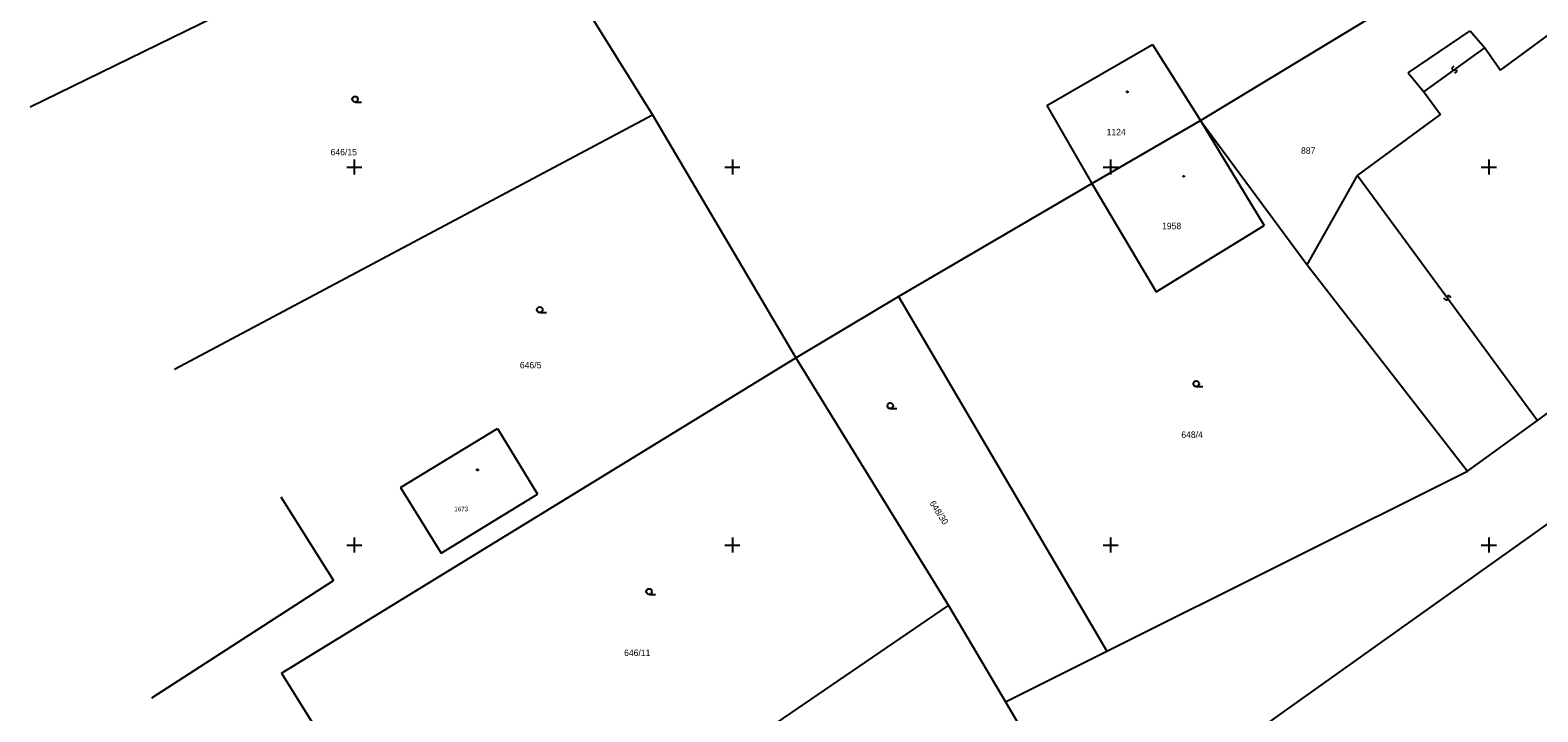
# Model space of a CAD drawing. Extents: x -492811 to -492366, y -1127107 to -1126748.
# Drawn here: x -492797.1 to -492717.4, y -1126848.8 to -1126812.8 of the extents above; entities that cross this region are included whole.
import ezdxf

# ---------------------------------------------------------------- set-up
doc = ezdxf.new("R2010")
doc.units = 0
doc.layers.add('katastrální mapa', color=7, linetype='Continuous')
doc.layers.add('síť', color=7, linetype='Continuous')

msp = doc.modelspace()

# ---------------------------------------------------------------- linework, layer by layer
at = {"layer": 'katastrální mapa'}
for p, q in [((-492735.24, -1126817.53), (-492712.31, -1126803.62)), ((-492771.89, -1126804.96), (-492764.22, -1126817.23)), ((-492797.14, -1126816.82), (-492778.84, -1126807.86)), ((-492719.38, -1126814.88), (-492714.08, -1126810.97)), ((-492724.26, -1126815.01), (-492720.98, -1126812.79)), ((-492720.98, -1126812.79), (-492720.21, -1126813.69)), ((-492743.37, -1126816.75), (-492737.78, -1126813.52)), ((-492737.78, -1126813.52), (-492735.24, -1126817.53)), ((-492723.44, -1126816.02), (-492720.21, -1126813.69)), ((-492720.21, -1126813.69), (-492719.38, -1126814.88)), ((-492724.26, -1126815.01), (-492723.44, -1126816.02)), ((-492721.94, -1126814.76), (-492721.95, -1126814.82)), ((-492721.95, -1126814.82), (-492721.92, -1126814.85)), ((-492721.84, -1126814.67), (-492721.94, -1126814.76)), ((-492721.92, -1126814.85), (-492721.87, -1126814.86)), ((-492721.87, -1126814.86), (-492721.78, -1126814.85)), ((-492721.71, -1126814.95), (-492721.81, -1126815.04)), ((-492721.78, -1126814.85), (-492721.73, -1126814.86)), ((-492721.73, -1126814.86), (-492721.7, -1126814.89)), ((-492721.7, -1126814.89), (-492721.71, -1126814.95)), ((-492779.96, -1126816.56), (-492779.61, -1126816.56)), ((-492739.15, -1126815.99), (-492739.09, -1126815.99)), ((-492739.15, -1126816.05), (-492739.15, -1126815.99)), ((-492739.09, -1126816.05), (-492739.15, -1126816.05)), ((-492739.09, -1126815.99), (-492739.09, -1126816.05)), ((-492723.44, -1126816.02), (-492722.56, -1126817.22)), ((-492789.5, -1126830.69), (-492764.22, -1126817.23)), ((-492764.22, -1126817.23), (-492756.64, -1126830.09)), ((-492743.37, -1126816.75), (-492741, -1126820.87)), ((-492726.94, -1126820.45), (-492722.56, -1126817.22)), ((-492741, -1126820.87), (-492735.24, -1126817.53)), ((-492735.24, -1126817.53), (-492729.6, -1126825.18)), ((-492735.24, -1126817.53), (-492731.88, -1126823.09)), ((-492736.17, -1126820.46), (-492736.11, -1126820.46)), ((-492736.17, -1126820.52), (-492736.17, -1126820.46)), ((-492736.11, -1126820.52), (-492736.17, -1126820.52)), ((-492736.11, -1126820.46), (-492736.11, -1126820.52)), ((-492729.6, -1126825.18), (-492726.94, -1126820.45)), ((-492726.94, -1126820.45), (-492717.43, -1126833.41)), ((-492751.22, -1126826.85), (-492741, -1126820.87)), ((-492741, -1126820.87), (-492737.59, -1126826.61)), ((-492737.59, -1126826.61), (-492731.88, -1126823.09)), ((-492733.15, -1126850.46), (-492697, -1126824.72)), ((-492729.6, -1126825.18), (-492721.12, -1126836.09)), ((-492756.64, -1126830.09), (-492751.22, -1126826.85)), ((-492751.22, -1126826.85), (-492740.2, -1126845.62)), ((-492722.27, -1126827.05), (-492722.37, -1126826.94)), ((-492722.18, -1126826.83), (-492722.19, -1126826.89)), ((-492722.19, -1126826.89), (-492722.18, -1126826.97)), ((-492722.18, -1126826.97), (-492722.19, -1126827.03)), ((-492722.15, -1126826.81), (-492722.18, -1126826.83)), ((-492722.1, -1126826.81), (-492722.15, -1126826.81)), ((-492722, -1126826.92), (-492722.1, -1126826.81)), ((-492770.19, -1126827.7), (-492769.84, -1126827.7)), ((-492722.22, -1126827.05), (-492722.27, -1126827.05)), ((-492722.19, -1126827.03), (-492722.22, -1126827.05)), ((-492783.84, -1126846.77), (-492756.64, -1126830.09)), ((-492756.64, -1126830.09), (-492748.58, -1126843.2)), ((-492717.43, -1126833.41), (-492713.11, -1126830.24)), ((-492735.47, -1126831.62), (-492735.12, -1126831.62)), ((-492751.65, -1126832.78), (-492751.3, -1126832.78)), ((-492777.55, -1126836.95), (-492772.43, -1126833.84)), ((-492772.43, -1126833.84), (-492770.3, -1126837.31)), ((-492721.12, -1126836.09), (-492717.43, -1126833.41)), ((-492773.51, -1126835.99), (-492773.45, -1126835.99)), ((-492773.51, -1126836.05), (-492773.51, -1126835.99)), ((-492773.45, -1126836.05), (-492773.51, -1126836.05)), ((-492773.45, -1126835.99), (-492773.45, -1126836.05)), ((-492740.2, -1126845.62), (-492721.12, -1126836.09)), ((-492777.55, -1126836.95), (-492775.41, -1126840.43)), ((-492775.41, -1126840.43), (-492770.3, -1126837.31)), ((-492783.88, -1126837.44), (-492781.1, -1126841.87)), ((-492790.71, -1126848.09), (-492781.1, -1126841.87)), ((-492764.41, -1126842.61), (-492764.06, -1126842.61)), ((-492774.94, -1126861.19), (-492748.58, -1126843.2)), ((-492748.58, -1126843.2), (-492745.56, -1126848.3)), ((-492745.56, -1126848.3), (-492740.2, -1126845.62)), ((-492783.84, -1126846.77), (-492782.25, -1126849.35)), ((-492745.56, -1126848.3), (-492740.87, -1126856.2))]:
    msp.add_line(p, q, dxfattribs=at)
for centre in [(-492779.96, -1126816.41), (-492770.19, -1126827.55), (-492735.47, -1126831.47), (-492751.65, -1126832.63), (-492764.41, -1126842.46)]:
    msp.add_circle(centre, 0.15, dxfattribs=at)
at = {"layer": 'síť'}
for p, q in [((-492780, -1126819.6), (-492780, -1126820.4)), ((-492760, -1126819.6), (-492760, -1126820.4)), ((-492740, -1126819.6), (-492740, -1126820.4)), ((-492720, -1126819.6), (-492720, -1126820.4)), ((-492780.4, -1126820), (-492779.6, -1126820)), ((-492760.4, -1126820), (-492759.6, -1126820)), ((-492740.4, -1126820), (-492739.6, -1126820)), ((-492720.4, -1126820), (-492719.6, -1126820)), ((-492780, -1126839.6), (-492780, -1126840.4)), ((-492760, -1126839.6), (-492760, -1126840.4)), ((-492740, -1126839.6), (-492740, -1126840.4)), ((-492720, -1126839.6), (-492720, -1126840.4)), ((-492780.4, -1126840), (-492779.6, -1126840)), ((-492760.4, -1126840), (-492759.6, -1126840)), ((-492740.4, -1126840), (-492739.6, -1126840)), ((-492720.4, -1126840), (-492719.6, -1126840))]:
    msp.add_line(p, q, dxfattribs=at)

# ---------------------------------------------------------------- texts
at = {"layer": 'katastrální mapa'}
for s, height, p in [('1124', 0.34, (-492740.21, -1126818.32)), ('887', 0.34, (-492729.93, -1126819.3)), ('646/15', 0.34, (-492781.25, -1126819.38)), ('1958', 0.34, (-492737.28, -1126823.29)), ('646/5', 0.34, (-492771.24, -1126830.65)), ('648/4', 0.34, (-492736.26, -1126834.33)), ('1673', 0.24, (-492774.71, -1126838.21)), ('646/11', 0.34, (-492765.73, -1126845.87))]:
    msp.add_text(s, height=height, dxfattribs=at).set_placement(p)
msp.add_text('648/30', height=0.34, rotation=302.526, dxfattribs=at).set_placement((-492749.59, -1126837.79))

doc.saveas('drawing.dxf')
